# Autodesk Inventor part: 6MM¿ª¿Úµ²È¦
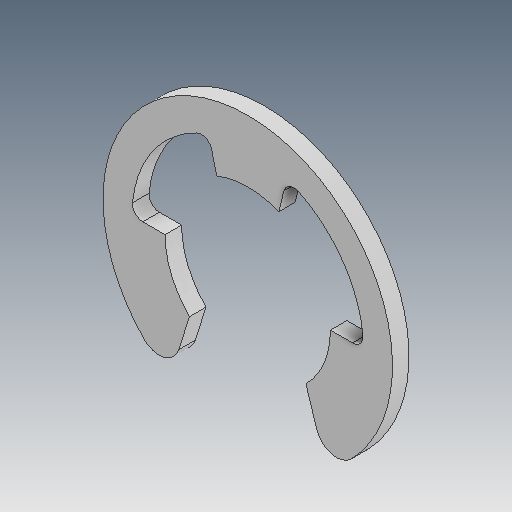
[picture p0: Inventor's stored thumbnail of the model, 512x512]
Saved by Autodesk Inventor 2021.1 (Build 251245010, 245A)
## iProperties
Created: 2019-04
Part Number: 6MM¿ª¿Úµ²È¦
Material: Ogólny
Document SubType Name: Modeling
Designer: user
Density: 1 g/cm^3
Appearance: Domyślna
Author: user
Revision Number: ÈÎºÎ
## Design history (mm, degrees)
feature "ÊäÈë1"
node "Bryła1"
